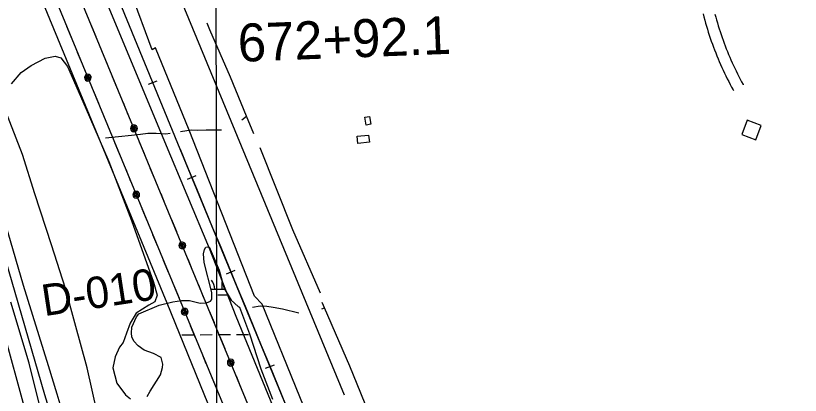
# Model space of a CAD drawing. Extents: x 3329297 to 3367176, y 649250 to 674653.
# Drawn here: x 3343401 to 3345468, y 665190 to 666191 of the extents above; entities that cross this region are included whole.
import ezdxf

# ---------------------------------------------------------------- set-up
doc = ezdxf.new("R2010")
doc.units = 0
for name, color, linetype in [('V-BLDG-OTLN', 7, 'Continuous'), ('V-GRID-MAJR', 7, 'Continuous'), ('V-LEVE-TOET', 7, 'Continuous'), ('V-RAIL-TRAK', 7, 'Continuous'), ('V-RIVR-RANG-IDEN', 7, 'Continuous'), ('V-ROAD-CNTR', 7, 'Continuous'), ('V-SITE-VEGE', 7, 'Continuous'), ('V-SURV-IDEN', 7, 'Continuous'), ('V-TOPO-SHOR', 7, 'Continuous'), ('V-UTIL-LINE', 7, 'Continuous'), ('V-WETL-SWMP', 7, 'Continuous')]:
    doc.layers.add(name, color=color, linetype=linetype)

msp = doc.modelspace()

# ---------------------------------------------------------------- linework, layer by layer
at = {"layer": 'V-BLDG-OTLN'}
for points in [[(3344324.3, 665903.1), (3344320.5, 665923.5), (3344333.1, 665925.9), (3344336.9, 665905.4)], [(3345313.7, 665878), (3345351.1, 665864), (3345365.2, 665901.5), (3345327.7, 665915.5)], [(3344300.6, 665873.6), (3344330.9, 665876.7), (3344332.9, 665857.6), (3344302.6, 665854.4)]]:
    msp.add_lwpolyline(points, close=True, dxfattribs=at)
at = {"layer": 'V-GRID-MAJR'}
msp.add_spline([(3343949.3, 654651.9), (3343938.7, 660710.3), (3343928.1, 666771.7), (3343917.5, 672833.1), (3343917.5, 672836.2)], degree=3, dxfattribs=at)
at = {"layer": 'V-LEVE-TOET'}
msp.add_lwpolyline([(3343370.7, 665352.2), (3343422.3, 665162.3), (3343480.5, 664955.1), (3343500.2, 664877.4), (3343501.8, 664860.7), (3343501.5, 664822.5), (3343480.6, 664539.9), (3343459, 664314.3), (3343441.6, 664085.3), (3343425.8, 663840.4), (3343416.1, 663664.3)], dxfattribs=at)
at = {"layer": 'V-RAIL-TRAK'}
for points in [[(3345872.4, 660898.3), (3345202.6, 662524.8), (3345202.6, 662524.8), (3343834.7, 665839), (3343834.7, 665839.1), (3342962.1, 667964.3), (3342962.1, 667964.3), (3342142.3, 669950.7), (3342142.3, 669950.7), (3341846.6, 670653.1)], [(3343834.7, 665839.1), (3342962.1, 667964.3)], [(3343750.8, 666010.4), (3343773.9, 666019.9)], [(3343853.5, 665760.7), (3343876.6, 665770.3)], [(3343956.5, 665511.1), (3343979.6, 665520.7)], [(3344059.5, 665261.6), (3344082.6, 665271.1)]]:
    msp.add_lwpolyline(points, dxfattribs=at)
msp.add_arc((6548955.2, 1986802.1), 3466661.3, 202.398581, 202.4578394, dxfattribs=at)
at = {"layer": 'V-ROAD-CNTR'}
for points in [[(3344266.9, 665190.7), (3343697.9, 666570.3)], [(3345211.9, 666195.9), (3345213.9, 666187.9), (3345216.1, 666179.9), (3345218.3, 666171.9), (3345220.7, 666163.9), (3345223.1, 666155.9), (3345225.5, 666148), (3345228.1, 666140.1), (3345230.7, 666132.2), (3345233.4, 666124.3), (3345236.2, 666116.5), (3345239.1, 666108.7), (3345242, 666100.9), (3345245, 666093.2), (3345248.1, 666085.5), (3345251.3, 666077.8), (3345254.5, 666070.1), (3345257.8, 666062.5), (3345261.2, 666054.9), (3345264.7, 666047.3), (3345268.2, 666039.8), (3345271.8, 666032.3), (3345275.5, 666024.9), (3345279.3, 666017.5), (3345283.1, 666010.1), (3345287, 666002.8), (3345290.9, 665995.5), (3345291.5, 665994.5)], [(3345242.9, 666195.5), (3345245, 666187.8), (3345247.2, 666180.1), (3345249.4, 666172.4), (3345251.7, 666164.7), (3345254.1, 666157), (3345256.6, 666149.4), (3345259.1, 666141.8), (3345261.7, 666134.2), (3345264.4, 666126.7), (3345267.2, 666119.2), (3345270, 666111.7), (3345272.9, 666104.2), (3345275.9, 666096.7), (3345279, 666089.3), (3345282.1, 666081.9), (3345285.3, 666074.6), (3345288.5, 666067.3), (3345291.9, 666060), (3345295.3, 666052.7), (3345298.8, 666045.5), (3345302.3, 666038.3), (3345305.9, 666031.2), (3345309.6, 666024), (3345313.4, 666017), (3345317.3, 666009.9), (3345317.8, 666009)], [(3343517.1, 665062.6), (3343477.9, 665191.4), (3343226.6, 666055.4)]]:
    msp.add_lwpolyline(points, dxfattribs=at)
at = {"layer": 'V-SITE-VEGE'}
for points in [[(3343390.1, 666011.3), (3343415.8, 666041.2), (3343442, 666060.1), (3343479.2, 666079.1), (3343504.8, 666084.9), (3343520.2, 666080.3), (3343537.5, 666056.9), (3343584.1, 665951), (3343646.2, 665807), (3343706, 665651.6), (3343764.4, 665489), (3343773.8, 665454.8), (3343768.1, 665436.6), (3343751.7, 665427.8), (3343718.4, 665407.2), (3343702.6, 665381), (3343693.4, 665354.1), (3343684.7, 665329.9), (3343675, 665317.2), (3343663.4, 665291.8), (3343657.1, 665263), (3343667.8, 665222.1), (3343690.7, 665191.6), (3343703.4, 665181.5)], [(3343616, 665145), (3343589.7, 665263), (3343557.1, 665381.3), (3343532.8, 665471.7), (3343495.9, 665587.6), (3343451.3, 665721.5), (3343419.3, 665825.2), (3343369.1, 665954.7)]]:
    msp.add_lwpolyline(points, dxfattribs=at)
at = {"layer": 'V-TOPO-SHOR'}
for p, q in [((3343997.2, 665916.4), (3344009.2, 665926.4)), ((3344207.7, 665418.7), (3344214.9, 665421.4))]:
    msp.add_line(p, q, dxfattribs=at)
for points in [[(3344249.2, 664942.3), (3344050.1, 665431.1), (3344030.4, 665452.2), (3343858, 665889.1), (3343769.1, 666106.8), (3343760.6, 666101.1), (3343705.5, 666251.5), (3343666, 666365.3), (3343619.4, 666450.9)], [(3343336.9, 666411), (3343473.3, 666422.5), (3343504.3, 666360.7), (3343526.8, 666349.5), (3343553.5, 666344), (3343591.5, 666334.2), (3343602.8, 666318.7), (3343793.4, 665859.4), (3343910.6, 665578.5), (3343981.3, 665398.7), (3344163.5, 664953.4), (3344373.8, 664477.2), (3344484, 664185), (3344509.3, 664199.1)], [(3343510.7, 665193.4), (3343487.7, 665267.8), (3343421.5, 665480), (3343354.4, 665709.5), (3343294.5, 665919.6), (3343257, 666046.4), (3343238.3, 666103.6), (3343223.4, 666134.5), (3343210, 666157.9), (3343196.7, 666172.9), (3343184.8, 666184.5), (3343172.2, 666195.5), (3343168.7, 666198.2), (3343163.9, 666199.5), (3343150.7, 666200)], [(3344028.2, 665879.6), (3344009.2, 665926.4), (3343967.3, 666029.1), (3343913, 666154.3), (3343905.8, 666171.6)], [(3343835.5, 665885.9), (3343863.3, 665890.4), (3343881.4, 665889.9), (3343902.9, 665890.2), (3343943.2, 665890)], [(3343637.5, 665869.6), (3343706.3, 665876.7), (3343729.9, 665879.1), (3343749.3, 665881.4), (3343771.6, 665881.7), (3343796.6, 665879.9), (3343807.7, 665881.4)], [(3344203.7, 665459.6), (3344131.4, 665626.4), (3344045.4, 665843)], [(3343454.9, 663805.6), (3343472.9, 664032.6), (3343482.6, 664201.5), (3343496.9, 664389.7), (3343503.4, 664536.4), (3343519, 664733), (3343522.5, 664849.2), (3343518.4, 664900.3), (3343506.3, 664983.2), (3343472.8, 665130), (3343437.1, 665275.5), (3343388.8, 665436.1)], [(3344850.8, 663877.8), (3344778.3, 664063.3), (3344713, 664214.8), (3344683.8, 664282.6), (3344616.4, 664451.4), (3344547.6, 664621.7), (3344468.2, 664807.8), (3344398.7, 664978.7), (3344343.3, 665115.7), (3344341.3, 665120.6), (3344281.1, 665267.3), (3344214.9, 665421.4), (3344212.4, 665427.1), (3344208.9, 665435.4)], [(3344024.7, 665422.7), (3344044.8, 665426.4), (3344062.9, 665425.3), (3344079, 665422.7), (3344104.1, 665418.8), (3344146.6, 665408.2)], [(3343570, 664632.7), (3343575.6, 664742), (3343581.4, 664890.7), (3343581.2, 664914.2), (3343577.2, 664953.6), (3343569.9, 664988.8), (3343565.5, 665008.8), (3343510.7, 665193.4)]]:
    msp.add_lwpolyline(points, dxfattribs=at)
at = {"layer": 'V-UTIL-LINE'}
for points in [[(3345932.1, 660508.5), (3345266.9, 662132.1), (3344424.6, 664170), (3343419, 666605.5), (3342586.6, 668628.9), (3341907.6, 670274.6), (3341535.6, 671146.2)], [(3341480.8, 671097), (3341874.4, 670184.1), (3342489.4, 668700.6), (3343600.8, 666004.9), (3344292.6, 664330.1), (3345012, 662588.2), (3345711.5, 660882.6)], [(3343930.4, 665113.3), (3343800.5, 665433.1), (3343407.6, 666385.3)], [(3343535.2, 666163.8), (3343548.2, 666132.4)], [(3343613.1, 666135.4), (3343600.1, 666166.8)], [(3343641.3, 666067), (3343628.4, 666098.4)], [(3343563.4, 666095.4), (3343576.4, 666064)], [(3343591.2, 666027.9), (3343592.8, 666030.4), (3343590.5, 666030.3), (3343589, 666027.9), (3343590.4, 666025.4), (3343593.6, 666026.5), (3343595.6, 666030.8), (3343592.4, 666033.7), (3343587.6, 666033.1), (3343585.6, 666029), (3343586.4, 666024.6), (3343590.7, 666022.3), (3343595.9, 666024.1), (3343599.6, 666031.4), (3343597.6, 666034.3), (3343594.7, 666036.3), (3343591.2, 666036.9), (3343587.8, 666036.3), (3343584.9, 666034.3), (3343582.9, 666031.4), (3343582.2, 666028), (3343582.9, 666024.5), (3343584.9, 666021.6), (3343587.8, 666019.6), (3343591.2, 666018.9), (3343594.7, 666019.6), (3343597.6, 666021.6), (3343599.5, 666024.5), (3343600.2, 666027.9), (3343599.6, 666031.4)], [(3343669.6, 665998.6), (3343656.6, 666030)], [(3343606.1, 665991.9), (3343619.1, 665960.4)], [(3343697.8, 665930.2), (3343684.9, 665961.6)], [(3343634.4, 665923.5), (3343647.3, 665892)], [(3343712.7, 665894.2), (3343711.2, 665891.7), (3343713.5, 665891.8), (3343714.9, 665894.2), (3343713.5, 665896.7), (3343710.3, 665895.6), (3343708.4, 665891.3), (3343711.5, 665888.4), (3343716.4, 665889), (3343718.3, 665893.1), (3343717.6, 665897.5), (3343713.3, 665899.8), (3343708.1, 665898), (3343704.4, 665890.7), (3343706.4, 665887.8), (3343709.3, 665885.8), (3343712.7, 665885.2), (3343716.2, 665885.8), (3343719.1, 665887.8), (3343721, 665890.7), (3343721.7, 665894.1), (3343721, 665897.6), (3343719.1, 665900.5), (3343716.2, 665902.5), (3343712.7, 665903.2), (3343709.3, 665902.5), (3343706.4, 665900.5), (3343704.4, 665897.6), (3343703.7, 665894.2), (3343704.4, 665890.7)], [(3343662.6, 665855.1), (3343675.6, 665823.7)], [(3343740.6, 665826.7), (3343727.6, 665858.1)], [(3343690.9, 665786.7), (3343703.9, 665755.3)], [(3343768.8, 665758.3), (3343755.8, 665789.7)], [(3343718.7, 665719.2), (3343720.3, 665721.7), (3343718, 665721.6), (3343716.5, 665719.2), (3343717.9, 665716.7), (3343721.1, 665717.8), (3343723, 665722.1), (3343719.9, 665725), (3343715.1, 665724.4), (3343713.1, 665720.3), (3343713.9, 665715.9), (3343718.2, 665713.6), (3343723.4, 665715.4), (3343727.1, 665722.7), (3343725.1, 665725.6), (3343722.2, 665727.6), (3343718.7, 665728.2), (3343715.3, 665727.6), (3343712.4, 665725.6), (3343710.4, 665722.7), (3343709.7, 665719.3), (3343710.4, 665715.8), (3343712.4, 665712.9), (3343715.3, 665710.9), (3343718.7, 665710.2), (3343722.2, 665710.9), (3343725.1, 665712.9), (3343727, 665715.8), (3343727.7, 665719.2), (3343727.1, 665722.7)], [(3343797.1, 665689.9), (3343784.1, 665721.3)], [(3343733.6, 665683.2), (3343746.6, 665651.7)], [(3343825.3, 665621.5), (3343812.3, 665652.9)], [(3343761.9, 665614.8), (3343774.9, 665583.3)], [(3343840.2, 665585.4), (3343838.6, 665583), (3343841, 665583.1), (3343842.4, 665585.4), (3343841, 665588), (3343837.8, 665586.9), (3343835.9, 665582.6), (3343839, 665579.7), (3343843.8, 665580.3), (3343845.8, 665584.4), (3343845, 665588.8), (3343840.8, 665591.1), (3343835.6, 665589.3), (3343831.9, 665582), (3343833.8, 665579.1), (3343836.7, 665577.1), (3343840.2, 665576.4), (3343843.6, 665577.1), (3343846.5, 665579.1), (3343848.5, 665582), (3343849.2, 665585.4), (3343848.5, 665588.9), (3343846.6, 665591.8), (3343843.6, 665593.7), (3343840.2, 665594.4), (3343836.8, 665593.8), (3343833.8, 665591.8), (3343831.9, 665588.9), (3343831.2, 665585.4), (3343831.9, 665582)], [(3343790.1, 665546.4), (3343803.1, 665515)], [(3343868, 665518), (3343855.1, 665549.4)], [(3343818.4, 665478), (3343831.4, 665446.6)], [(3343896.3, 665449.6), (3343883.3, 665481)], [(3343846.2, 665410.5), (3343847.8, 665413), (3343845.5, 665412.9), (3343844.1, 665410.5), (3343845.5, 665408), (3343848.7, 665409.1), (3343850.6, 665413.4), (3343847.4, 665416.3), (3343842.6, 665415.7), (3343840.6, 665411.6), (3343841.4, 665407.2), (3343845.7, 665404.9), (3343850.9, 665406.7), (3343854.6, 665414), (3343852.6, 665416.9), (3343849.7, 665418.9), (3343846.3, 665419.5), (3343842.8, 665418.9), (3343839.9, 665416.9), (3343837.9, 665414), (3343837.2, 665410.6), (3343837.9, 665407.1), (3343839.9, 665404.2), (3343842.8, 665402.2), (3343846.2, 665401.5), (3343849.7, 665402.2), (3343852.6, 665404.2), (3343854.6, 665407.1), (3343855.2, 665410.5), (3343854.6, 665414)], [(3343924.5, 665381.2), (3343911.5, 665412.6)], [(3343861.1, 665374.5), (3343874.1, 665343)], [(3343952.8, 665312.8), (3343939.8, 665344.2)], [(3343889.4, 665306.1), (3343902.4, 665274.6)], [(3343967.7, 665276.7), (3343966.1, 665274.3), (3343968.4, 665274.4), (3343969.9, 665276.7), (3343968.4, 665279.3), (3343965.2, 665278.1), (3343963.3, 665273.9), (3343966.5, 665271), (3343971.3, 665271.5), (3343973.3, 665275.7), (3343972.5, 665280.1), (3343968.2, 665282.4), (3343963, 665280.6), (3343959.3, 665273.3), (3343961.3, 665270.4), (3343964.2, 665268.4), (3343967.6, 665267.7), (3343971.1, 665268.4), (3343974, 665270.3), (3343976, 665273.3), (3343976.7, 665276.7), (3343976, 665280.1), (3343974, 665283.1), (3343971.1, 665285), (3343967.7, 665285.7), (3343964.2, 665285), (3343961.3, 665283.1), (3343959.3, 665280.2), (3343958.7, 665276.7), (3343959.3, 665273.3)], [(3343917.7, 665237.7), (3343930.6, 665206.3)], [(3343995.5, 665209.3), (3343982.5, 665240.7)]]:
    msp.add_lwpolyline(points, dxfattribs=at)
at = {"layer": 'V-WETL-SWMP'}
for p, q in [((3343945.4, 665470.5), (3343945.4, 665489.3)), ((3343915.4, 665470.5), (3343951, 665470.5)), ((3343933.4, 665455.1), (3343957.4, 665455.1)), ((3343838.8, 665350.2), (3343870.8, 665350.3)), ((3343886.8, 665350.3), (3343918.8, 665350.4)), ((3343934.8, 665350.4), (3343966.8, 665350.5)), ((3343982.8, 665350.5), (3344014.8, 665350.6))]:
    msp.add_line(p, q, dxfattribs=at)
msp.add_lwpolyline([(3343747.6, 665187.3), (3343755.1, 665201.3), (3343782.4, 665244), (3343787.8, 665263.6), (3343789, 665272.6), (3343784.7, 665290), (3343764.4, 665300.8), (3343739.9, 665309.6), (3343723.8, 665321.2), (3343712.5, 665333.6), (3343706.8, 665344.7), (3343706, 665354.4), (3343707.2, 665369.7), (3343719.4, 665397.7), (3343725.5, 665405.4), (3343778.8, 665428.3), (3343814.9, 665437.1), (3343837.8, 665440.1), (3343859.3, 665440.4), (3343887.2, 665433.8), (3343903.9, 665434), (3343914.3, 665438.3), (3343917, 665441.8), (3343917.7, 665445.2), (3343917.5, 665461.9), (3343897.8, 665541), (3343896.1, 665563.2), (3343898.7, 665575.1), (3343902.1, 665580.7), (3343910.5, 665582.2), (3343936.9, 665520.6), (3343950, 665472.1), (3343969.2, 665441), (3343987.5, 665424.5), (3343991, 665422.5), (3344016.9, 665352.6), (3344047.2, 665260.5), (3344078, 665180.2)], dxfattribs=at)
msp.add_arc((3343890.2, 665470.9), 35.2, 359.3365, 40.8801, dxfattribs=at)

# ---------------------------------------------------------------- texts
at = {"layer": 'V-RIVR-RANG-IDEN'}
msp.add_text('D-010', height=83, rotation=8.6633, dxfattribs=at).set_placement((3343476.3, 665398.8))
at = {"layer": 'V-SURV-IDEN'}
msp.add_text('672+92.1', height=100, rotation=2.1872, dxfattribs=at).set_placement((3343988.2, 666069.5))

doc.saveas('drawing.dxf')
